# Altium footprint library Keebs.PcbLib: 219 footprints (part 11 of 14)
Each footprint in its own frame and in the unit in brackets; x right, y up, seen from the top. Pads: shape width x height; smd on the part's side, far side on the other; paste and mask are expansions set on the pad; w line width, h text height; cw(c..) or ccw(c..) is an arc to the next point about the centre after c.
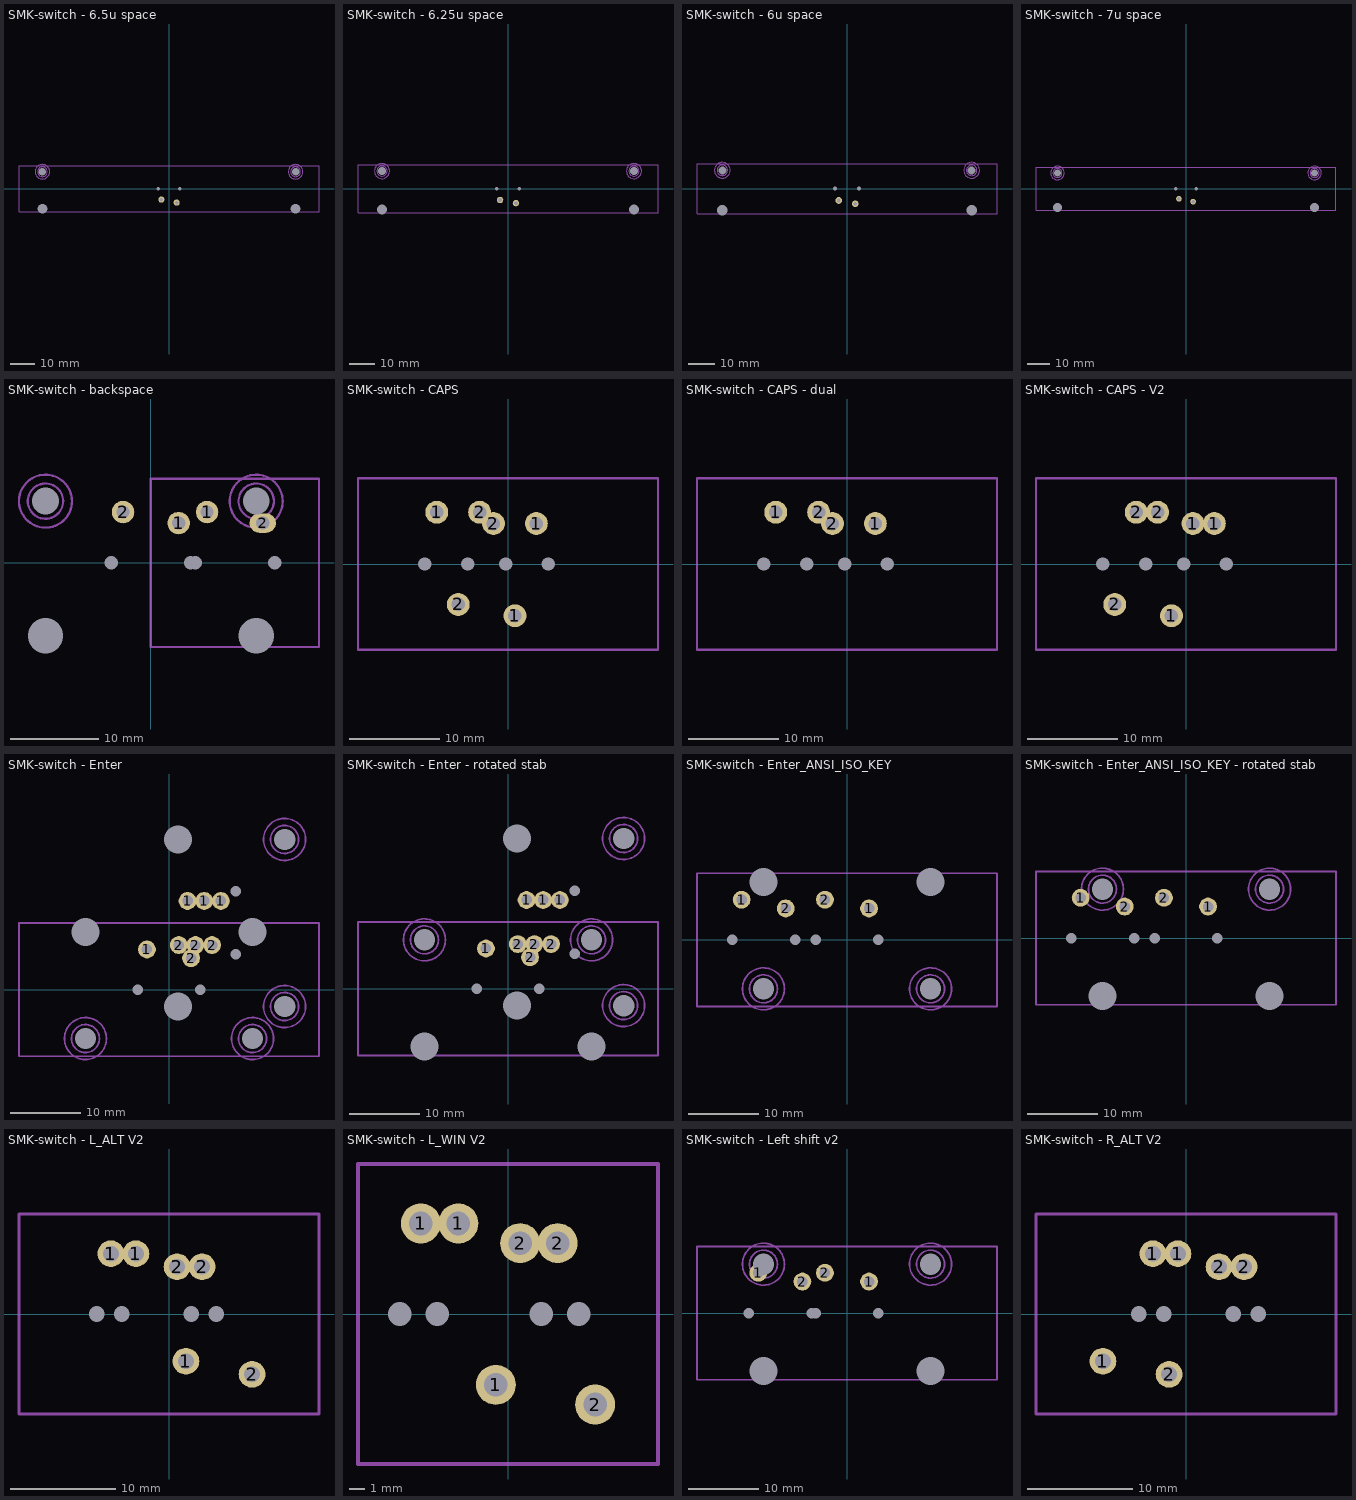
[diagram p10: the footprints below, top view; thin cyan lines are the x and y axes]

## SMK-switch - 6.5u space [mm]
pads (9):
  round 2.54 hole 1.5 mask-0.5: 1(3.15,-5.75) 2(-3.15,-4.5)
  round 1.524 hole 4 unplated: ""(-52.25,-8.255) ""(52.25,-8.255)
  round 1.524 hole 3.048 unplated: ""(-52.25,6.985) ""(52.25,6.985)
  round 1 hole 1.5 unplated: ""(-4.5,0) ""(4.5,0)
  round 1 on Mech13: ""(0,0)
Mechanical 13:
  lines w0.254: -61.912,-9.525 61.912,-9.525 61.912,9.525 -61.912,9.525 -61.912,-9.525
  text ".Designator" at -3.575,-3.7 h0.7
Mechanical 15:
  circle w0.254: c52.25,6.985 r2
  circle w0.254: c52.25,6.985 r3
  circle w0.254: c-52.25,6.985 r2
  circle w0.254: c-52.25,6.985 r3

## SMK-switch - 6.25u space [mm]
pads (9):
  round 2.54 hole 1.5 mask-0.5: 1(3.15,-5.75) 2(-3.15,-4.5)
  round 1.524 hole 4 unplated: ""(-50,-8.255) ""(50,-8.255)
  round 1.524 hole 3.048 unplated: ""(-50,6.985) ""(50,6.985)
  round 1 hole 1.5 unplated: ""(-4.5,0) ""(4.5,0)
  round 1 on Mech13: ""(0,0)
Mechanical 13:
  lines w0.254: -59.531,-9.525 59.531,-9.525 59.531,9.525 -59.531,9.525 -59.531,-9.525
  text ".Designator" at -3.575,-3.7 h0.7
Mechanical 15:
  circle w0.254: c-50,6.985 r3
  circle w0.254: c-50,6.985 r2
  circle w0.254: c50,6.985 r3
  circle w0.254: c50,6.985 r2

## SMK-switch - 6u space [mm]
pads (9):
  round 2.54 hole 1.499 mask-0.5: 1(3.15,-5.75) 2(-3.15,-4.5)
  round 1.524 hole 4 unplated: ""(-47.5,-8.255) ""(47.5,-8.255)
  round 1.524 hole 3.048 unplated: ""(-47.5,6.985) ""(47.5,6.985)
  round 1 hole 1.5 unplated: ""(-4.5,0) ""(4.5,0)
  round 1 on Mech13: ""(0,0)
Mechanical 13:
  lines w0.254: -57.15,-9.525 -57.15,9.525 57.15,9.525 57.15,-9.525 -57.15,-9.525
  text ".Designator" at -3.575,-3.7 h0.7
Mechanical 15:
  circle w0.254: c-47.5,6.985 r3
  circle w0.254: c-47.5,6.985 r2
  circle w0.254: c47.5,6.985 r3
  circle w0.254: c47.5,6.985 r2

## SMK-switch - 7u space [mm]
pads (9):
  round 2.54 hole 1.5 mask-0.5: 1(3.15,-5.75) 2(-3.15,-4.5)
  round 1.524 hole 4 unplated: ""(-57.15,-8.255) ""(57.15,-8.255)
  round 1.524 hole 3.048 unplated: ""(-57.15,6.985) ""(57.15,6.985)
  round 1 hole 1.5 unplated: ""(-4.5,0) ""(4.5,0)
  round 1 on Mech13: ""(0,0)
Mechanical 13:
  lines w0.254: -66.675,-9.525 -66.675,9.525 66.675,9.525 66.675,-9.525 -66.675,-9.525
  text ".Designator" at -3.575,-3.7 h0.7
Mechanical 15:
  circle w0.254: c-57.15,6.985 r3
  circle w0.254: c-57.15,6.985 r2
  circle w0.254: c57.15,6.985 r3
  circle w0.254: c57.15,6.985 r2

## SMK-switch - backspace [mm]
pads (14):
  round 2.54 hole 1.5 mask-0.5: 1(3.15,4.5) 1(6.375,5.75) 2(-3.15,5.75)
  oval 3x2.2 hole 1.5 mask-0.7: 2(12.675,4.5)
  round 1.524 hole 4 unplated: ""(-11.938,-8.255) ""(11.938,-8.255)
  round 1.524 hole 3.048 unplated: ""(-11.938,6.985) ""(11.938,6.985)
  round 1 hole 1.5 unplated: ""(-4.5,0) ""(4.5,0) ""(5.025,0) ""(14.025,0)
  round 1 on Mech13: ""(0,0) ""(9.525,0)
Mechanical 13:
  lines w0.254: 0,-9.525 19.05,-9.525 19.05,9.525 0,9.525 0,-9.525
  text ".Designator" at 6.65,3.75 h0.7
Mechanical 15:
  circle w0.254: c11.938,6.985 r2
  circle w0.254: c11.938,6.985 r3
  circle w0.254: c-11.938,6.985 r2
  circle w0.254: c-11.938,6.985 r3

## SMK-switch - CAPS [mm]
pads (13):
  round 2.54 hole 1.5 mask-0.5: 1(-7.912,5.75) 1(0.769,-5.75) 1(3.15,4.5) 2(-5.531,-4.5) 2(-3.15,5.75) 2(-1.613,4.5)
  round 1 hole 1.5 unplated: ""(-9.263,0) ""(-4.5,0) ""(-0.262,0) ""(4.5,0)
  round 1 on Mech13: ""(-4.763,0) ""(-2.381,0) ""(0,0)
Mechanical 13:
  lines w0.254: -16.669,-9.525 16.669,-9.525 ; -16.669,-9.525 16.669,-9.525 ; -16.669,-9.525 -16.669,9.525 16.669,9.525 16.669,-9.525
  text ".Designator" at -7.85,-7.5 h0.7

## SMK-switch - CAPS - dual [mm]
pads (10):
  round 2.54 hole 1.5 mask-0.5: 1(-7.912,5.75) 1(3.15,4.5) 2(-3.15,5.75) 2(-1.613,4.5)
  round 1 hole 1.5 unplated: ""(-9.263,0) ""(-4.5,0) ""(-0.262,0) ""(4.5,0)
  round 1 on Mech13: ""(-4.763,0) ""(0,0)
Mechanical 13:
  lines w0.254: -16.669,-9.525 -16.669,9.525 16.669,9.525 16.669,-9.525 ; -16.669,-9.525 16.669,-9.525 ; -16.669,-9.525 16.669,-9.525
  text ".Designator" at -7.85,-7.5 h0.7

## SMK-switch - CAPS - V2 [mm]
pads (13):
  round 2.54 hole 1.5 mask-0.5: 1(-1.613,-5.75) 1(0.769,4.5) 1(3.15,4.5) 2(-7.912,-4.5) 2(-5.531,5.75) 2(-3.15,5.75)
  round 1 hole 1.5 unplated: ""(-9.263,0) ""(-4.5,0) ""(-0.262,0) ""(4.5,0)
  round 1 on Mech13: ""(-4.763,0) ""(-2.381,0) ""(0,0)
Mechanical 13:
  lines w0.254: -16.669,-9.525 16.669,-9.525 ; -16.669,-9.525 16.669,-9.525 ; -16.669,-9.525 -16.669,9.525 16.669,9.525 16.669,-9.525
  text ".Designator" at -7.85,-7.5 h0.7

## SMK-switch - Enter [mm]
pads (24):
  round 2.54 hole 1.5 mask-0.5: 1(-3.15,5.75) 1(2.649,12.68) 1(5.03,12.68) 1(7.411,12.68) 2(1.399,6.38) 2(3.15,4.5) 2(3.78,6.38) 2(6.161,6.38)
  round 1.524 hole 3.048 unplated: ""(-11.938,-6.985) ""(11.938,-6.985) ""(16.515,-2.408) ""(16.515,21.468)
  round 1.524 hole 4 unplated: ""(-11.938,8.255) ""(1.275,-2.408) ""(1.275,21.468) ""(11.938,8.255)
  round 1 hole 1.5 unplated: ""(-4.5,0) ""(4.5,0) ""(9.53,5.03) ""(9.53,14.03)
  round 1 on Mech13: ""(0,0) ""(7.149,9.53) ""(9.53,9.53) ""(11.911,9.53)
Mechanical 13:
  lines w0.254: -21.431,-9.525 21.431,-9.525 21.431,9.525 -21.431,9.525 -21.431,-9.525
  text ".Designator" at 7.85,1.8 h0.7
Mechanical 15:
  circle w0.254: c-11.938,-6.985 r3
  circle w0.254: c-11.938,-6.985 r2
  circle w0.254: c11.938,-6.985 r3
  circle w0.254: c11.938,-6.985 r2
  circle w0.254: c16.515,-2.408 r3
  circle w0.254: c16.515,-2.408 r2
  circle w0.254: c16.515,21.468 r3
  circle w0.254: c16.515,21.468 r2

## SMK-switch - Enter - rotated stab [mm]
pads (24):
  round 2.54 hole 1.5 mask-0.5: 1(-3.15,5.75) 1(2.649,12.68) 1(5.03,12.68) 1(7.411,12.68) 2(1.399,6.38) 2(3.15,4.5) 2(3.78,6.38) 2(6.161,6.38)
  round 1.524 hole 4 unplated: ""(-11.938,-8.255) ""(1.275,21.468) ""(11.938,-8.255)
  round 1.524 hole 3.048 unplated: ""(-11.938,6.985) ""(11.938,6.985) ""(16.515,-2.408) ""(16.515,21.468)
  round 1 hole 1.5 unplated: ""(-4.5,0) ""(4.5,0) ""(9.53,5.03) ""(9.53,14.03)
  round 1 on Mech13: ""(0,0) ""(7.149,9.53) ""(9.53,9.53) ""(11.911,9.53)
  round 1.524 hole 3.988 unplated: ""(1.275,-2.408)
Mechanical 13:
  lines w0.254: -21.431,-9.525 21.431,-9.525 21.431,9.525 -21.431,9.525 -21.431,-9.525
  text ".Designator" at 7.85,1.8 h0.7
Mechanical 15:
  circle w0.254: c16.515,21.468 r3
  circle w0.254: c16.515,21.468 r2
  circle w0.254: c16.515,-2.408 r3
  circle w0.254: c16.515,-2.408 r2
  circle w0.254: c11.938,6.985 r3
  circle w0.254: c11.938,6.985 r2
  circle w0.254: c-11.938,6.985 r3
  circle w0.254: c-11.938,6.985 r2

## SMK-switch - Enter_ANSI_ISO_KEY [mm]
pads (16):
  round 2.54 hole 1.5 mask-0.5: 1(-15.056,5.75) 1(3.15,4.5) 2(-8.756,4.5) 2(-3.15,5.75)
  round 1 hole 1.5 unplated: ""(-16.406,0) ""(-7.406,0) ""(-4.5,0) ""(4.5,0)
  round 1.524 hole 3.048 unplated: ""(-11.938,-6.985) ""(11.938,-6.985)
  round 1.524 hole 4 unplated: ""(-11.938,8.255) ""(11.938,8.255)
  round 1 on Mech13: ""(-11.906,0) ""(-11.906,0) ""(0,0) ""(0,0)
Mechanical 13:
  lines w0.254: -21.431,-9.525 21.431,-9.525 21.431,9.525 -21.431,9.525 -21.431,-9.525
  text ".Designator" at 7.85,1.8 h0.7
Mechanical 15:
  circle w0.254: c11.938,-6.985 r2
  circle w0.254: c11.938,-6.985 r3
  circle w0.254: c-11.938,-6.985 r2
  circle w0.254: c-11.938,-6.985 r3

## SMK-switch - Enter_ANSI_ISO_KEY - rotated stab [mm]
pads (16):
  round 2.54 hole 1.5 mask-0.5: 1(-15.056,5.75) 1(3.15,4.5) 2(-8.756,4.5) 2(-3.15,5.75)
  round 1 hole 1.5 unplated: ""(-16.406,0) ""(-7.406,0) ""(-4.5,0) ""(4.5,0)
  round 1.524 hole 4 unplated: ""(-11.938,-8.255) ""(11.938,-8.255)
  round 1.524 hole 3.048 unplated: ""(-11.938,6.985) ""(11.938,6.985)
  round 1 on Mech13: ""(-11.906,0) ""(-11.906,0) ""(0,0) ""(0,0)
Mechanical 13:
  lines w0.254: -21.431,-9.525 21.431,-9.525 21.431,9.525 -21.431,9.525 -21.431,-9.525
  text ".Designator" at 7.85,1.8 h0.7
Mechanical 15:
  circle w0.254: c-11.938,6.985 r3
  circle w0.254: c-11.938,6.985 r2
  circle w0.254: c11.938,6.985 r3
  circle w0.254: c11.938,6.985 r2

## SMK-switch - L_ALT V2 [mm]
pads (13):
  round 2.54 hole 1.5 mask-0.5: 1(-5.531,5.75) 1(-3.15,5.75) 1(1.613,-4.5) 2(0.769,4.5) 2(3.15,4.5) 2(7.912,-5.75)
  round 1 hole 1.5 unplated: ""(-6.881,0) ""(-4.5,0) ""(2.119,0) ""(4.5,0)
  round 1 on Mech13: ""(-2.381,0) ""(0,0) ""(4.763,0)
Mechanical 13:
  lines w0.254: -14.287,-9.525 14.287,-9.525 14.287,9.525 -14.287,9.525 -14.287,-9.525
  text ".Designator" at 2.9,2.625 h0.7

## SMK-switch - L_WIN V2 [mm]
pads (13):
  round 2.54 hole 1.5 mask-0.5: 1(-5.531,5.75) 1(-3.15,5.75) 1(-0.769,-4.5) 2(0.769,4.5) 2(3.15,4.5) 2(5.531,-5.75)
  round 1 hole 1.5 unplated: ""(-6.881,0) ""(-4.5,0) ""(2.119,0) ""(4.5,0)
  round 1 on Mech13: ""(-2.381,0) ""(0,0) ""(2.381,0)
Mechanical 13:
  lines w0.254: -9.525,-9.525 -9.525,9.525 9.525,9.525 9.525,-9.525 -9.525,-9.525
  text ".Designator" at -1.925,-7.85 h0.7

## SMK-switch - Left shift v2 [mm]
pads (14):
  round 2.54 hole 1.5 mask-0.5: 1(-12.675,5.75) 1(3.15,4.5) 2(-6.375,4.5) 2(-3.15,5.75)
  round 1 hole 1.5 unplated: ""(-14.025,0) ""(-5.025,0) ""(-4.5,0) ""(4.5,0)
  round 1.524 hole 4 unplated: ""(-11.938,-8.255) ""(11.938,-8.255)
  round 1.524 hole 3.048 unplated: ""(-11.938,6.985) ""(11.938,6.985)
  round 1 on Mech13: ""(-9.525,0) ""(0,0)
Mechanical 13:
  lines w0.254: -21.431,-9.525 21.431,-9.525 21.431,9.525 -21.431,9.525 -21.431,-9.525
  text ".Designator" at -5.45,-3.925 h0.7
Mechanical 15:
  circle w0.254: c-11.938,6.985 r3
  circle w0.254: c-11.938,6.985 r2
  circle w0.254: c11.938,6.985 r3
  circle w0.254: c11.938,6.985 r2

## SMK-switch - R_ALT V2 [mm] "Common tsangan and WK bottom + AEK"
pads (13):
  round 2.54 hole 1.5 mask-0.5: 1(-7.912,-4.5) 1(-3.15,5.75) 1(-0.769,5.75) 2(-1.613,-5.75) 2(3.15,4.5) 2(5.531,4.5)
  round 1 on Mech13: ""(-4.763,0) ""(0,0) ""(2.381,0)
  round 1 hole 1.5 unplated: ""(-4.5,0) ""(-2.119,0) ""(4.5,0) ""(6.881,0)
Mechanical 13:
  lines w0.254: -14.287,-9.525 14.287,-9.525 14.287,9.525 -14.287,9.525 -14.287,-9.525
  text ".Designator" at -10.675,-5.325 h0.7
